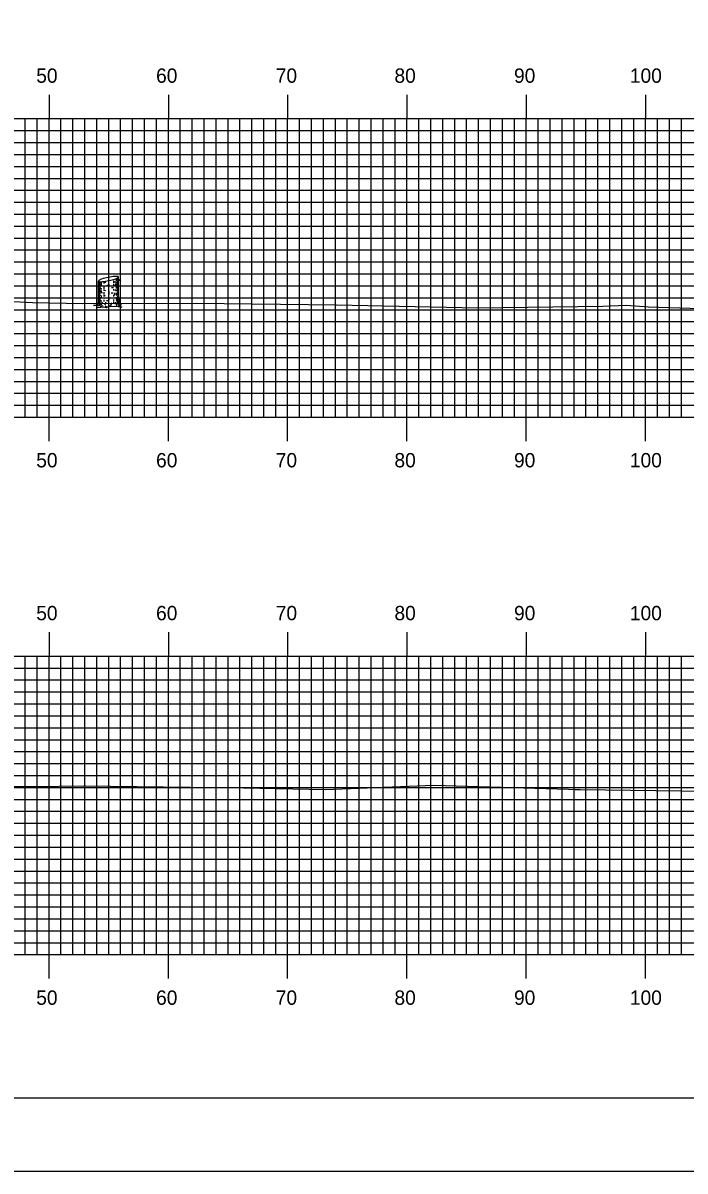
# Model space of a CAD drawing. Extents: x 1798388 to 1798731, y 442591 to 442811.
# Drawn here: x 1798601.3 to 1798656.8, y 442590.5 to 442686.7 of the extents above; entities that cross this region are included whole.
import ezdxf

# ---------------------------------------------------------------- set-up
doc = ezdxf.new("R2010")
doc.units = 0
for name, color, linetype in [('BORDER', 7, 'Continuous'), ('H_V ANNOTATION', 7, 'Continuous'), ('M_Trees_Conifer_Pay', 7, 'Continuous'), ('MAJOR', 7, 'Continuous'), ('MINOR', 7, 'Continuous'), ('PLOT BOUNDARY', 7, 'Continuous'), ('S_Roadway_Centerline', 7, 'Continuous')]:
    doc.layers.add(name, color=color, linetype=linetype)

msp = doc.modelspace()

# ---------------------------------------------------------------- linework, layer by layer
at = {"layer": 'BORDER'}
msp.add_lwpolyline([(1798403.871, 442596.665), (1798723.871, 442596.665), (1798723.871, 442806.665), (1798403.871, 442806.665)], close=True, dxfattribs=at)
at = {"layer": 'M_Trees_Conifer_Pay'}
for p, q in [((1798607.62, 442663.345), (1798607.62, 442665.067)), ((1798607.668, 442665.03), (1798607.668, 442664.559)), ((1798607.726, 442665.019), (1798607.726, 442664.921)), ((1798607.726, 442664.847), (1798607.726, 442664.643)), ((1798607.851, 442665.011), (1798607.851, 442664.779)), ((1798608.071, 442665.031), (1798608.071, 442664.863)), ((1798608.477, 442664.8), (1798608.477, 442664.704)), ((1798608.867, 442665.073), (1798608.867, 442664.874)), ((1798608.867, 442664.816), (1798608.867, 442664.727)), ((1798609.095, 442665.269), (1798609.095, 442665.046)), ((1798609.095, 442664.958), (1798609.095, 442664.91)), ((1798609.152, 442664.775), (1798609.101, 442664.715)), ((1798609.213, 442665.33), (1798609.213, 442665.168)), ((1798609.213, 442665.1), (1798609.213, 442664.972)), ((1798609.213, 442664.785), (1798609.213, 442664.449)), ((1798609.284, 442663.756), (1798609.284, 442665.403)), ((1798607.668, 442664.494), (1798607.668, 442664.186)), ((1798607.668, 442664.139), (1798607.668, 442663.647)), ((1798607.726, 442664.585), (1798607.726, 442664.385)), ((1798607.726, 442664.338), (1798607.726, 442664.002)), ((1798607.726, 442663.949), (1798607.726, 442663.813)), ((1798607.851, 442664.738), (1798607.851, 442664.664)), ((1798607.851, 442664.26), (1798607.851, 442664.122)), ((1798607.851, 442663.85), (1798607.851, 442663.708)), ((1798608.071, 442664.626), (1798608.071, 442664.389)), ((1798608.071, 442664.145), (1798608.071, 442663.992)), ((1798608.071, 442663.949), (1798608.071, 442663.776)), ((1798608.477, 442664.186), (1798608.477, 442664.112)), ((1798608.477, 442664.087), (1798608.477, 442663.939)), ((1798608.867, 442664.38), (1798608.867, 442664.275)), ((1798608.867, 442663.908), (1798608.867, 442663.761)), ((1798609.095, 442664.575), (1798609.095, 442664.443)), ((1798609.095, 442664.332), (1798609.095, 442664.223)), ((1798609.095, 442664.087), (1798609.095, 442663.945)), ((1798609.213, 442664.412), (1798609.213, 442664.25)), ((1798609.213, 442664.202), (1798609.213, 442663.986)), ((1798609.213, 442663.955), (1798609.213, 442663.881)), ((1798609.213, 442663.84), (1798609.213, 442663.667)), ((1798607.668, 442663.593), (1798607.668, 442663.345)), ((1798607.726, 442663.714), (1798607.726, 442663.336)), ((1798607.851, 442663.446), (1798607.851, 442663.352)), ((1798607.851, 442662.952), (1798608.014, 442663.016)), ((1798608.071, 442663.498), (1798608.071, 442663.345)), ((1798608.288, 442662.888), (1798608.162, 442662.952)), ((1798608.477, 442663.647), (1798608.477, 442663.494)), ((1798608.867, 442663.529), (1798608.867, 442663.441)), ((1798609.095, 442663.718), (1798609.095, 442663.546))]:
    msp.add_line(p, q, dxfattribs=at)
for points in [[(1798609.068, 442664.863), (1798609.037, 442664.779), (1798609.033, 442664.711), (1798609.064, 442664.647)], [(1798609.101, 442664.901), (1798609.138, 442664.826), (1798609.185, 442664.883), (1798609.243, 442664.952), (1798609.335, 442665.145), (1798609.4, 442665.193), (1798609.431, 442665.199)], [(1798609.116, 442664.647), (1798609.152, 442664.775), (1798609.216, 442664.89), (1798609.247, 442664.958), (1798609.316, 442665.104)], [(1798609.33, 442665.133), (1798609.406, 442665.141), (1798609.478, 442665.042)], [(1798607.799, 442664.373), (1798607.793, 442664.468), (1798607.837, 442664.445), (1798607.837, 442664.351)], [(1798608.939, 442663.974), (1798608.951, 442663.897), (1798608.998, 442663.908), (1798608.986, 442664.074)], [(1798609.284, 442663.756), (1798609.335, 442663.494), (1798609.352, 442663.22), (1798609.41, 442663.095), (1798609.545, 442663.064), (1798609.315, 442663.027), (1798609.315, 442663.027), (1798609.321, 442662.979), (1798609.568, 442662.885), (1798609.294, 442662.901), (1798608.939, 442662.922), (1798608.617, 442662.911), (1798608.624, 442662.994), (1798608.475, 442662.911), (1798608.288, 442662.888), (1798608.313, 442662.821), (1798608.045, 442662.864), (1798607.824, 442662.837), (1798607.532, 442662.854), (1798607.82, 442662.911), (1798607.851, 442662.952), (1798607.689, 442663.01), (1798607.452, 442663.021), (1798607.211, 442663.021), (1798607.553, 442663.078), (1798607.594, 442663.158), (1798607.62, 442663.345)], [(1798607.668, 442663.298), (1798607.647, 442663.22), (1798607.627, 442663.126)], [(1798607.746, 442663.278), (1798607.752, 442663.162), (1798607.699, 442663.074), (1798607.689, 442663.01)], [(1798607.909, 442663.305), (1798607.909, 442663.173), (1798607.82, 442663.074)], [(1798608.135, 442663.064), (1798608.203, 442663.158), (1798608.23, 442663.298)], [(1798608.624, 442662.994), (1798608.698, 442663.135), (1798608.708, 442663.237)], [(1798608.874, 442663.362), (1798608.885, 442663.237), (1798608.959, 442663.193)], [(1798609.152, 442662.973), (1798609.138, 442663.111), (1798609.064, 442663.24)], [(1798609.111, 442663.467), (1798609.185, 442663.362), (1798609.19, 442663.189), (1798609.315, 442663.027)], [(1798609.21, 442663.613), (1798609.216, 442663.467), (1798609.263, 442663.399), (1798609.274, 442663.2)]]:
    msp.add_lwpolyline(points, dxfattribs=at)
for centre, radius, start, end in [((1798607.652, 442664.889), 0.0334, 163.94846, 180), ((1798607.652, 442664.889), 0.0334, 180, 196.05154), ((1798607.647, 442665.067), 0.0264, 169.2194, 180.03145), ((1798607.643, 442665.067), 0.0226, 180.03145, 191.7194), ((1798607.663, 442664.892), 0.0441, 196.05154, 210), ((1798607.652, 442665.066), 0.0314, 156.51582, 169.2194), ((1798607.643, 442665.067), 0.0226, 191.7194, 203.40735), ((1798607.646, 442665.068), 0.0264, 203.40735, 214.2194), ((1798607.671, 442665.058), 0.0527, 146.7194, 156.51582), ((1798607.651, 442665.071), 0.0314, 214.2194, 226.92298), ((1798607.679, 442664.901), 0.0624, 210, 228.74941), ((1798607.695, 442665.042), 0.0817, 132.38868, 146.7194), ((1798607.665, 442665.087), 0.0527, 226.92298, 236.7194), ((1798607.681, 442665.111), 0.0817, 236.7194, 251.05013), ((1798607.751, 442664.984), 0.172, 228.74941, 240), ((1798607.809, 442664.917), 0.251, 124.2194, 132.38868), ((1798607.736, 442665.271), 0.251, 251.05013, 259.2194), ((1798607.95, 442665.329), 0.571, 240, 240.33672), ((1798608.119, 442664.461), 0.802, 108.05939, 124.2194), ((1798607.839, 442665.812), 0.802, 259.2194, 275.37941), ((1798607.95, 442665.329), 0.571, 246.85973, 257.98457), ((1798609.476, 442660.3), 5.179, 101.7194, 108.05939), ((1798607.429, 442670.17), 5.179, 275.37941, 281.7194), ((1798608.453, 442669.079), 4.124, 264.6955, 266.73309), ((1798609.476, 442660.3), 5.179, 95.37941, 101.7194), ((1798607.429, 442670.17), 5.179, 281.7194, 288.05939), ((1798608.451, 442668.846), 4.124, 275.78493, 277.05584), ((1798608.453, 442669.079), 4.124, 276.23804, 278.1032), ((1798609.066, 442664.658), 0.802, 79.2194, 95.37941), ((1798608.786, 442666.008), 0.802, 288.05939, 304.2194), ((1798608.953, 442665.562), 0.571, 278.1032, 284.36665), ((1798608.953, 442665.716), 0.571, 284.43166, 292.41325), ((1798608.953, 442665.562), 0.571, 297.0237, 300), ((1798609.169, 442665.199), 0.251, 71.05013, 79.2194), ((1798609.095, 442665.553), 0.251, 304.2194, 312.38868), ((1798609.153, 442665.371), 0.172, 300, 311.25059), ((1798609.153, 442665.217), 0.172, 300, 311.25059), ((1798609.224, 442665.359), 0.0817, 56.7194, 71.05013), ((1798609.209, 442665.428), 0.0817, 312.38868, 326.7194), ((1798609.225, 442665.288), 0.0624, 311.25059, 330), ((1798609.225, 442665.134), 0.0624, 311.25059, 330), ((1798609.24, 442665.383), 0.0527, 46.92298, 56.7194), ((1798609.254, 442665.398), 0.0314, 34.2194, 46.92298), ((1798609.234, 442665.412), 0.0527, 326.7194, 336.51582), ((1798609.241, 442665.279), 0.0441, 330, 343.94846), ((1798609.241, 442665.125), 0.0441, 330, 343.94846), ((1798609.258, 442665.401), 0.0264, 23.40735, 34.2194), ((1798609.253, 442665.404), 0.0314, 336.51582, 349.2194), ((1798609.262, 442665.403), 0.0226, 11.7194, 23.40735), ((1798609.251, 442665.276), 0.0334, 343.94846, 354.21506), ((1798609.251, 442665.122), 0.0334, 343.94846, 354.21506), ((1798609.262, 442665.403), 0.0226, 0.03145, 11.7194), ((1798609.258, 442665.403), 0.0264, 349.2194, 0.03145), ((1798607.652, 442664.442), 0.0334, 163.94846, 180), ((1798607.652, 442664.442), 0.0334, 180, 196.05154), ((1798607.652, 442664.232), 0.0334, 163.94846, 180), ((1798607.652, 442664.232), 0.0334, 180, 196.05154), ((1798607.652, 442663.995), 0.0334, 163.94846, 180), ((1798607.652, 442663.995), 0.0334, 180, 196.05154), ((1798607.652, 442663.798), 0.0334, 163.94846, 180), ((1798607.663, 442664.445), 0.0441, 196.05154, 210), ((1798607.663, 442664.235), 0.0441, 196.05154, 210), ((1798607.663, 442663.998), 0.0441, 196.05154, 210), ((1798607.679, 442664.454), 0.0624, 210, 228.74941), ((1798607.679, 442664.244), 0.0624, 210, 228.74941), ((1798607.679, 442664.007), 0.0624, 210, 228.74941), ((1798607.751, 442664.537), 0.172, 228.74941, 240), ((1798607.751, 442664.327), 0.172, 228.74941, 240), ((1798607.751, 442664.09), 0.172, 228.74941, 240), ((1798607.95, 442664.882), 0.571, 240, 240.33672), ((1798607.95, 442664.672), 0.571, 240, 246.85973), ((1798607.95, 442664.435), 0.571, 240, 246.85973), ((1798607.952, 442665.118), 0.571, 240, 247.05866), ((1798607.95, 442664.672), 0.571, 259.27072, 261.8968), ((1798608.451, 442668.189), 4.124, 261.8968, 263.14738), ((1798608.451, 442668.399), 4.124, 264.08098, 266.66759), ((1798608.451, 442667.953), 4.124, 264.71603, 266.31934), ((1798608.451, 442668.846), 4.124, 268.07512, 270), ((1798608.451, 442668.846), 4.124, 270, 270.35814), ((1798608.451, 442668.189), 4.124, 270, 270.35814), ((1798608.451, 442668.189), 4.124, 273.14934, 275.45691), ((1798608.452, 442668.635), 4.124, 273.70524, 275.95043), ((1798608.451, 442668.399), 4.124, 277.61247, 278.1032), ((1798608.952, 442664.882), 0.571, 278.1032, 286.92962), ((1798608.953, 442665.118), 0.571, 284.44928, 297.04285), ((1798608.952, 442664.435), 0.571, 285.39827, 297.18959), ((1798608.952, 442664.882), 0.571, 297.18959, 300), ((1798608.952, 442664.672), 0.571, 297.18959, 300), ((1798609.151, 442664.537), 0.172, 300, 311.25059), ((1798609.151, 442664.327), 0.172, 300, 311.25059), ((1798609.224, 442664.454), 0.0624, 311.25059, 330), ((1798609.224, 442664.244), 0.0624, 311.25059, 330), ((1798609.239, 442664.445), 0.0441, 330, 343.94846), ((1798609.239, 442664.235), 0.0441, 330, 343.94846), ((1798609.239, 442663.801), 0.0441, 330, 343.94846), ((1798609.25, 442664.442), 0.0334, 343.94846, 354.21506), ((1798609.25, 442664.232), 0.0334, 343.94846, 354.21506), ((1798609.25, 442663.798), 0.0334, 343.94846, 354.21506), ((1798609.251, 442664.678), 0.0334, 343.94846, 354.21506), ((1798607.652, 442663.602), 0.0334, 163.94846, 180), ((1798607.652, 442663.602), 0.0334, 180, 196.05154), ((1798607.652, 442663.382), 0.0334, 163.94846, 180), ((1798607.652, 442663.382), 0.0334, 180, 196.05154), ((1798607.663, 442663.605), 0.0441, 196.05154, 210), ((1798607.663, 442663.385), 0.0441, 196.05154, 210), ((1798607.679, 442663.614), 0.0624, 210, 228.74941), ((1798607.679, 442663.394), 0.0624, 210, 228.74941), ((1798607.751, 442663.697), 0.172, 228.74941, 240), ((1798607.751, 442663.477), 0.172, 228.74941, 240), ((1798607.94, 442664.244), 0.571, 241.23686, 248.02677), ((1798607.95, 442664.042), 0.571, 240, 246.85973), ((1798607.95, 442663.822), 0.571, 240, 244.53138), ((1798608.451, 442667.339), 4.124, 262.44379, 263.51202), ((1798608.451, 442667.755), 4.124, 263.49906, 265.83975), ((1798608.451, 442667.559), 4.124, 267.81166, 270), ((1798608.451, 442667.559), 4.124, 270, 270.13279), ((1798608.451, 442667.559), 4.124, 275.78493, 276.78961), ((1798608.451, 442667.339), 4.124, 277.36842, 278.1032), ((1798608.952, 442663.822), 0.571, 278.1032, 281.63703), ((1798608.952, 442664.042), 0.571, 288.50673, 297.27208), ((1798608.952, 442664.237), 0.571, 289.29072, 300), ((1798609.151, 442663.892), 0.172, 300, 311.25059), ((1798609.151, 442663.477), 0.172, 300, 311.25059), ((1798609.224, 442663.81), 0.0624, 311.25059, 330), ((1798609.224, 442663.394), 0.0624, 311.25059, 330), ((1798609.239, 442663.385), 0.0441, 330, 343.94846), ((1798609.25, 442663.382), 0.0334, 343.94846, 354.21506)]:
    msp.add_arc(centre, radius, start, end, dxfattribs=at)
at = {"layer": 'MAJOR'}
for p, q in [((1798603.471, 442680.669), (1798603.471, 442678.665)), ((1798613.471, 442680.669), (1798613.471, 442678.665)), ((1798623.471, 442680.669), (1798623.471, 442678.665)), ((1798633.471, 442680.669), (1798633.471, 442678.665)), ((1798643.471, 442680.669), (1798643.471, 442678.665)), ((1798653.471, 442680.669), (1798653.471, 442678.665)), ((1798413.471, 442678.665), (1798693.471, 442678.665)), ((1798413.471, 442678.665), (1798693.471, 442678.665)), ((1798603.471, 442653.665), (1798603.471, 442678.665)), ((1798613.471, 442653.665), (1798613.471, 442678.665)), ((1798623.471, 442653.665), (1798623.471, 442678.665)), ((1798633.471, 442653.665), (1798633.471, 442678.665)), ((1798643.471, 442653.665), (1798643.471, 442678.665)), ((1798653.471, 442653.665), (1798653.471, 442678.665)), ((1798413.471, 442673.665), (1798693.471, 442673.665)), ((1798413.471, 442668.665), (1798693.471, 442668.665)), ((1798413.471, 442663.665), (1798693.471, 442663.665)), ((1798413.471, 442658.665), (1798693.471, 442658.665)), ((1798413.471, 442653.665), (1798693.471, 442653.665)), ((1798413.471, 442653.665), (1798693.471, 442653.665)), ((1798603.471, 442651.661), (1798603.471, 442653.665)), ((1798613.471, 442651.661), (1798613.471, 442653.665)), ((1798623.471, 442651.661), (1798623.471, 442653.665)), ((1798633.471, 442651.661), (1798633.471, 442653.665)), ((1798643.471, 442651.661), (1798643.471, 442653.665)), ((1798653.471, 442651.661), (1798653.471, 442653.665)), ((1798603.471, 442635.669), (1798603.471, 442633.665)), ((1798613.471, 442635.669), (1798613.471, 442633.665)), ((1798623.471, 442635.669), (1798623.471, 442633.665)), ((1798633.471, 442635.669), (1798633.471, 442633.665)), ((1798643.471, 442635.669), (1798643.471, 442633.665)), ((1798653.471, 442635.669), (1798653.471, 442633.665)), ((1798413.471, 442633.665), (1798693.471, 442633.665)), ((1798413.471, 442633.665), (1798693.471, 442633.665)), ((1798603.471, 442608.665), (1798603.471, 442633.665)), ((1798613.471, 442608.665), (1798613.471, 442633.665)), ((1798623.471, 442608.665), (1798623.471, 442633.665)), ((1798633.471, 442608.665), (1798633.471, 442633.665)), ((1798643.471, 442608.665), (1798643.471, 442633.665)), ((1798653.471, 442608.665), (1798653.471, 442633.665)), ((1798413.471, 442628.665), (1798693.471, 442628.665)), ((1798413.471, 442623.665), (1798693.471, 442623.665)), ((1798413.471, 442618.665), (1798693.471, 442618.665)), ((1798413.471, 442613.665), (1798693.471, 442613.665)), ((1798413.471, 442608.665), (1798693.471, 442608.665)), ((1798413.471, 442608.665), (1798693.471, 442608.665)), ((1798603.471, 442606.661), (1798603.471, 442608.665)), ((1798613.471, 442606.661), (1798613.471, 442608.665)), ((1798623.471, 442606.661), (1798623.471, 442608.665)), ((1798633.471, 442606.661), (1798633.471, 442608.665)), ((1798643.471, 442606.661), (1798643.471, 442608.665)), ((1798653.471, 442606.661), (1798653.471, 442608.665))]:
    msp.add_line(p, q, dxfattribs=at)
at = {"layer": 'MINOR'}
for p, q in [((1798601.471, 442653.665), (1798601.471, 442678.665)), ((1798602.471, 442653.665), (1798602.471, 442678.665)), ((1798604.471, 442653.665), (1798604.471, 442678.665)), ((1798605.471, 442653.665), (1798605.471, 442678.665)), ((1798606.471, 442653.665), (1798606.471, 442678.665)), ((1798607.471, 442653.665), (1798607.471, 442678.665)), ((1798608.471, 442653.665), (1798608.471, 442678.665)), ((1798609.471, 442653.665), (1798609.471, 442678.665)), ((1798610.471, 442653.665), (1798610.471, 442678.665)), ((1798611.471, 442653.665), (1798611.471, 442678.665)), ((1798612.471, 442653.665), (1798612.471, 442678.665)), ((1798614.471, 442653.665), (1798614.471, 442678.665)), ((1798615.471, 442653.665), (1798615.471, 442678.665)), ((1798616.471, 442653.665), (1798616.471, 442678.665)), ((1798617.471, 442653.665), (1798617.471, 442678.665)), ((1798618.471, 442653.665), (1798618.471, 442678.665)), ((1798619.471, 442653.665), (1798619.471, 442678.665)), ((1798620.471, 442653.665), (1798620.471, 442678.665)), ((1798621.471, 442653.665), (1798621.471, 442678.665)), ((1798622.471, 442653.665), (1798622.471, 442678.665)), ((1798624.471, 442653.665), (1798624.471, 442678.665)), ((1798625.471, 442653.665), (1798625.471, 442678.665)), ((1798626.471, 442653.665), (1798626.471, 442678.665)), ((1798627.471, 442653.665), (1798627.471, 442678.665)), ((1798628.471, 442653.665), (1798628.471, 442678.665)), ((1798629.471, 442653.665), (1798629.471, 442678.665)), ((1798630.471, 442653.665), (1798630.471, 442678.665)), ((1798631.471, 442653.665), (1798631.471, 442678.665)), ((1798632.471, 442653.665), (1798632.471, 442678.665)), ((1798634.471, 442653.665), (1798634.471, 442678.665)), ((1798635.471, 442653.665), (1798635.471, 442678.665)), ((1798636.471, 442653.665), (1798636.471, 442678.665)), ((1798637.471, 442653.665), (1798637.471, 442678.665)), ((1798638.471, 442653.665), (1798638.471, 442678.665)), ((1798639.471, 442653.665), (1798639.471, 442678.665)), ((1798640.471, 442653.665), (1798640.471, 442678.665)), ((1798641.471, 442653.665), (1798641.471, 442678.665)), ((1798642.471, 442653.665), (1798642.471, 442678.665)), ((1798644.471, 442653.665), (1798644.471, 442678.665)), ((1798645.471, 442653.665), (1798645.471, 442678.665)), ((1798646.471, 442653.665), (1798646.471, 442678.665)), ((1798647.471, 442653.665), (1798647.471, 442678.665)), ((1798648.471, 442653.665), (1798648.471, 442678.665)), ((1798649.471, 442653.665), (1798649.471, 442678.665)), ((1798650.471, 442653.665), (1798650.471, 442678.665)), ((1798651.471, 442653.665), (1798651.471, 442678.665)), ((1798652.471, 442653.665), (1798652.471, 442678.665)), ((1798654.471, 442653.665), (1798654.471, 442678.665)), ((1798655.471, 442653.665), (1798655.471, 442678.665)), ((1798656.471, 442653.665), (1798656.471, 442678.665)), ((1798413.471, 442677.665), (1798693.471, 442677.665)), ((1798413.471, 442676.665), (1798693.471, 442676.665)), ((1798413.471, 442675.665), (1798693.471, 442675.665)), ((1798413.471, 442674.665), (1798693.471, 442674.665)), ((1798413.471, 442672.665), (1798693.471, 442672.665)), ((1798413.471, 442671.665), (1798693.471, 442671.665)), ((1798413.471, 442670.665), (1798693.471, 442670.665)), ((1798413.471, 442669.665), (1798693.471, 442669.665)), ((1798413.471, 442667.665), (1798693.471, 442667.665)), ((1798413.471, 442666.665), (1798693.471, 442666.665)), ((1798413.471, 442665.665), (1798693.471, 442665.665)), ((1798413.471, 442664.665), (1798693.471, 442664.665)), ((1798413.471, 442662.665), (1798693.471, 442662.665)), ((1798413.471, 442661.665), (1798693.471, 442661.665)), ((1798413.471, 442660.665), (1798693.471, 442660.665)), ((1798413.471, 442659.665), (1798693.471, 442659.665)), ((1798413.471, 442657.665), (1798693.471, 442657.665)), ((1798413.471, 442656.665), (1798693.471, 442656.665)), ((1798413.471, 442655.665), (1798693.471, 442655.665)), ((1798413.471, 442654.665), (1798693.471, 442654.665)), ((1798601.471, 442608.665), (1798601.471, 442633.665)), ((1798602.471, 442608.665), (1798602.471, 442633.665)), ((1798604.471, 442608.665), (1798604.471, 442633.665)), ((1798605.471, 442608.665), (1798605.471, 442633.665)), ((1798606.471, 442608.665), (1798606.471, 442633.665)), ((1798607.471, 442608.665), (1798607.471, 442633.665)), ((1798608.471, 442608.665), (1798608.471, 442633.665)), ((1798609.471, 442608.665), (1798609.471, 442633.665)), ((1798610.471, 442608.665), (1798610.471, 442633.665)), ((1798611.471, 442608.665), (1798611.471, 442633.665)), ((1798612.471, 442608.665), (1798612.471, 442633.665)), ((1798614.471, 442608.665), (1798614.471, 442633.665)), ((1798615.471, 442608.665), (1798615.471, 442633.665)), ((1798616.471, 442608.665), (1798616.471, 442633.665)), ((1798617.471, 442608.665), (1798617.471, 442633.665)), ((1798618.471, 442608.665), (1798618.471, 442633.665)), ((1798619.471, 442608.665), (1798619.471, 442633.665)), ((1798620.471, 442608.665), (1798620.471, 442633.665)), ((1798621.471, 442608.665), (1798621.471, 442633.665)), ((1798622.471, 442608.665), (1798622.471, 442633.665)), ((1798624.471, 442608.665), (1798624.471, 442633.665)), ((1798625.471, 442608.665), (1798625.471, 442633.665)), ((1798626.471, 442608.665), (1798626.471, 442633.665)), ((1798627.471, 442608.665), (1798627.471, 442633.665)), ((1798628.471, 442608.665), (1798628.471, 442633.665)), ((1798629.471, 442608.665), (1798629.471, 442633.665)), ((1798630.471, 442608.665), (1798630.471, 442633.665)), ((1798631.471, 442608.665), (1798631.471, 442633.665)), ((1798632.471, 442608.665), (1798632.471, 442633.665)), ((1798634.471, 442608.665), (1798634.471, 442633.665)), ((1798635.471, 442608.665), (1798635.471, 442633.665)), ((1798636.471, 442608.665), (1798636.471, 442633.665)), ((1798637.471, 442608.665), (1798637.471, 442633.665)), ((1798638.471, 442608.665), (1798638.471, 442633.665)), ((1798639.471, 442608.665), (1798639.471, 442633.665)), ((1798640.471, 442608.665), (1798640.471, 442633.665)), ((1798641.471, 442608.665), (1798641.471, 442633.665)), ((1798642.471, 442608.665), (1798642.471, 442633.665)), ((1798644.471, 442608.665), (1798644.471, 442633.665)), ((1798645.471, 442608.665), (1798645.471, 442633.665)), ((1798646.471, 442608.665), (1798646.471, 442633.665)), ((1798647.471, 442608.665), (1798647.471, 442633.665)), ((1798648.471, 442608.665), (1798648.471, 442633.665)), ((1798649.471, 442608.665), (1798649.471, 442633.665)), ((1798650.471, 442608.665), (1798650.471, 442633.665)), ((1798651.471, 442608.665), (1798651.471, 442633.665)), ((1798652.471, 442608.665), (1798652.471, 442633.665)), ((1798654.471, 442608.665), (1798654.471, 442633.665)), ((1798655.471, 442608.665), (1798655.471, 442633.665)), ((1798656.471, 442608.665), (1798656.471, 442633.665)), ((1798413.471, 442632.665), (1798693.471, 442632.665)), ((1798413.471, 442631.665), (1798693.471, 442631.665)), ((1798413.471, 442630.665), (1798693.471, 442630.665)), ((1798413.471, 442629.665), (1798693.471, 442629.665)), ((1798413.471, 442627.665), (1798693.471, 442627.665)), ((1798413.471, 442626.665), (1798693.471, 442626.665)), ((1798413.471, 442625.665), (1798693.471, 442625.665)), ((1798413.471, 442624.665), (1798693.471, 442624.665)), ((1798413.471, 442622.665), (1798693.471, 442622.665)), ((1798413.471, 442621.665), (1798693.471, 442621.665)), ((1798413.471, 442620.665), (1798693.471, 442620.665)), ((1798413.471, 442619.665), (1798693.471, 442619.665)), ((1798413.471, 442617.665), (1798693.471, 442617.665)), ((1798413.471, 442616.665), (1798693.471, 442616.665)), ((1798413.471, 442615.665), (1798693.471, 442615.665)), ((1798413.471, 442614.665), (1798693.471, 442614.665)), ((1798413.471, 442612.665), (1798693.471, 442612.665)), ((1798413.471, 442611.665), (1798693.471, 442611.665)), ((1798413.471, 442610.665), (1798693.471, 442610.665)), ((1798413.471, 442609.665), (1798693.471, 442609.665))]:
    msp.add_line(p, q, dxfattribs=at)
at = {"layer": 'PLOT BOUNDARY'}
msp.add_lwpolyline([(1798387.684, 442590.547), (1798727.684, 442590.547), (1798727.684, 442810.547), (1798387.684, 442810.547)], close=True, dxfattribs=at)
at = {"layer": 'S_Roadway_Centerline'}
for points in [[(1798584.086, 442664.224), (1798602.093, 442663.271), (1798606.309, 442663.191), (1798615.813, 442663.21), (1798627.556, 442663.081), (1798639.409, 442662.81), (1798649.898, 442662.961), (1798651.851, 442663.051), (1798653.725, 442662.909), (1798670.339, 442662.376), (1798677.906, 442662.346), (1798685.723, 442662.392), (1798693.093, 442662.252), (1798693.471, 442662.253)], [(1798596.584, 442622.756), (1798602.182, 442622.746), (1798606.4, 442622.808), (1798619.782, 442622.632), (1798626.635, 442622.485), (1798635.708, 442622.868), (1798647, 442622.514), (1798647.562, 442622.498), (1798647.996, 442622.497), (1798658.581, 442622.367), (1798670.157, 442622.188), (1798670.819, 442622.187), (1798671.532, 442622.163), (1798692.206, 442621.837), (1798693.471, 442621.826)]]:
    msp.add_lwpolyline(points, dxfattribs=at)

# ---------------------------------------------------------------- texts
at = {"layer": 'H_V ANNOTATION'}
for s, p in [('50', (1798602.4, 442681.665)), ('60', (1798612.443, 442681.665)), ('70', (1798622.475, 442681.665)), ('80', (1798632.422, 442681.665)), ('90', (1798642.443, 442681.665)), ('100', (1798652.154, 442681.665)), ('50', (1798602.4, 442649.465)), ('60', (1798612.443, 442649.465)), ('70', (1798622.475, 442649.465)), ('80', (1798632.422, 442649.465)), ('90', (1798642.443, 442649.465)), ('100', (1798652.154, 442649.465)), ('50', (1798602.4, 442636.665)), ('60', (1798612.443, 442636.665)), ('70', (1798622.475, 442636.665)), ('80', (1798632.422, 442636.665)), ('90', (1798642.443, 442636.665)), ('100', (1798652.154, 442636.665)), ('50', (1798602.4, 442604.465)), ('60', (1798612.443, 442604.465)), ('70', (1798622.475, 442604.465)), ('80', (1798632.422, 442604.465)), ('90', (1798642.443, 442604.465)), ('100', (1798652.154, 442604.465))]:
    msp.add_text(s, height=1.2, dxfattribs=at).set_placement(p)

doc.saveas('drawing.dxf')
